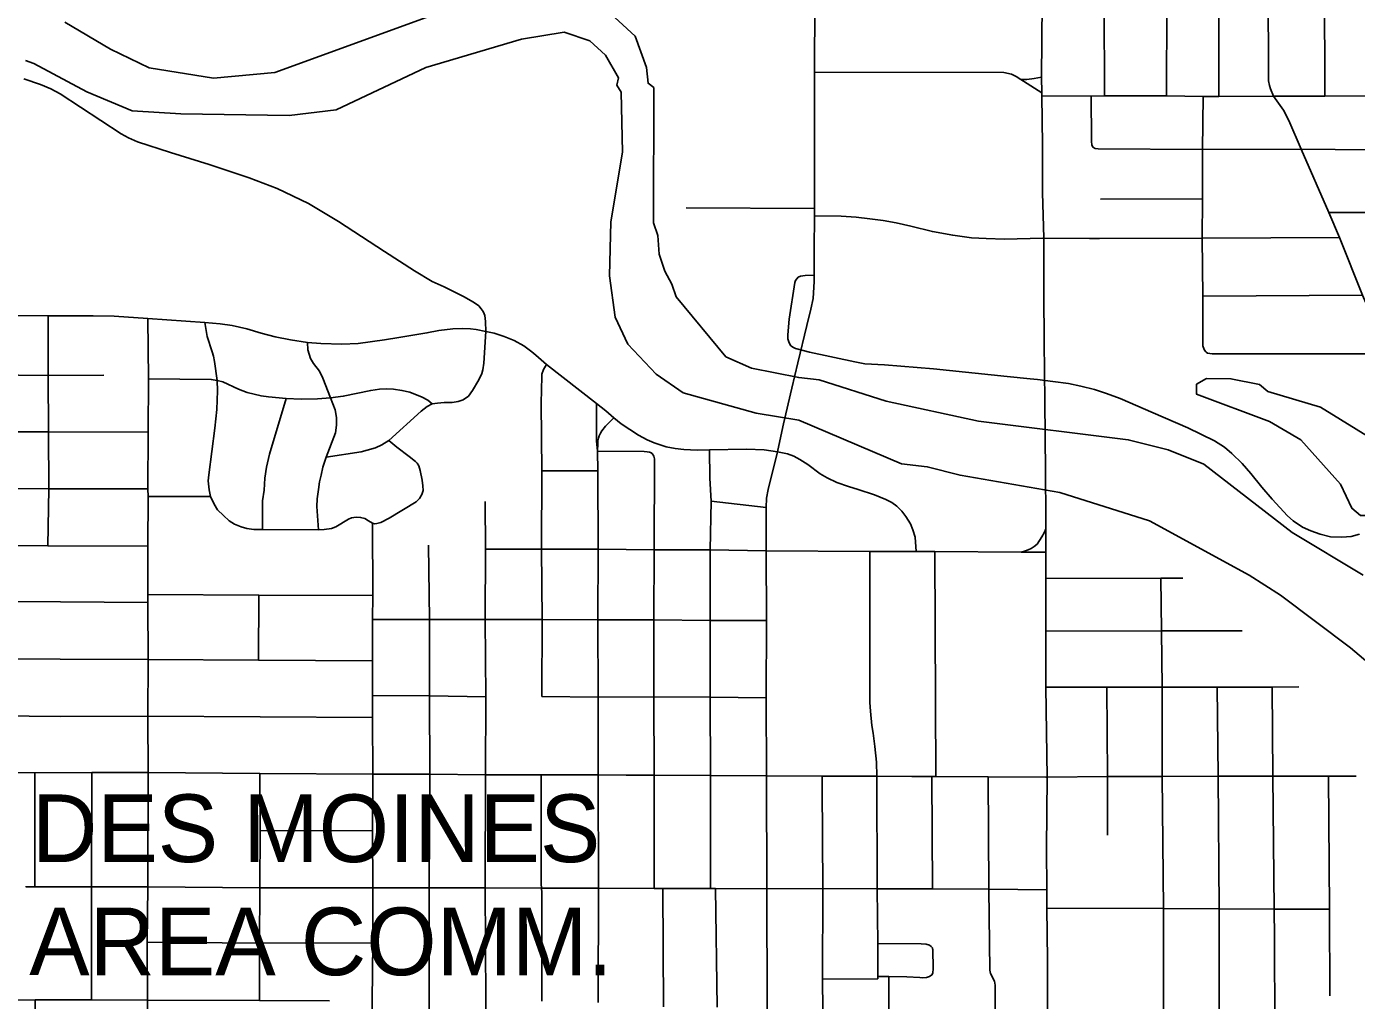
# Model space of a CAD drawing. Extents: x -1403959 to 81668, y -1400582 to 11018.
# Drawn here: x 7081.4 to 7223.9, y 8354.4 to 8458.9 of the extents above; entities that cross this region are included whole.
import ezdxf

# ---------------------------------------------------------------- set-up
doc = ezdxf.new("R2010")
doc.units = 0
for name, color, linetype in [('tdCiSectNmbr', 7, 'Continuous'), ('tdCiSectTwpRng', 7, 'Continuous'), ('tdCoStrucSec', 7, 'Continuous'), ('tdCoSurfBitum', 7, 'Continuous')]:
    doc.layers.add(name, color=color, linetype=linetype)

msp = doc.modelspace()

# ---------------------------------------------------------------- linework, layer by layer
at = {"layer": 'tdCiSectNmbr'}
for points in [[(7165.83, 8431.54), (7165.83, 8432.21), (7165.83, 8435.02), (7165.86, 8438.57), (7165.86, 8439.36), (7165.87, 8454), (7165.91, 8461.53), (7165.92, 8461.77), (7165.94, 8469.53), (7165.94, 8470.99), (7165.96, 8480.28), (7165.96, 8480.78), (7165.96, 8480.78)], [(7190.84, 8351.52), (7190.85, 8358.78), (7190.77, 8364.35), (7190.75, 8366.29), (7190.74, 8370.74), (7190.79, 8378.4), (7190.66, 8388.02), (7190.66, 8394.05), (7190.64, 8399.68), (7190.66, 8402.51), (7190.64, 8405.03), (7190.64, 8406.28), (7190.62, 8411.12), (7190.55, 8418.76), (7190.49, 8425.02), (7190.43, 8430.21), (7190.43, 8434.35), (7190.43, 8435.97), (7190.43, 8436.2), (7190.3, 8441.07), (7190.28, 8446.2), (7190.21, 8451.46), (7190.21, 8451.76), (7190.2, 8453.47), (7190.26, 8461.4)], [(7081.1, 8453.29), (7082.89, 8452.67), (7084.01, 8452.19), (7085, 8451.66), (7091.53, 8447.39), (7092.32, 8446.94), (7093.3, 8446.53), (7096.85, 8445.39), (7100.99, 8444.08), (7105.26, 8442.67), (7108.25, 8441.51), (7111.63, 8439.9), (7114.84, 8437.97), (7119.76, 8434.77)], [(7119.76, 8434.77), (7122.98, 8432.7), (7124.89, 8431.56)], [(7124.89, 8431.56), (7126.16, 8430.96), (7128.23, 8429.95), (7129.31, 8429.33), (7129.88, 8428.93), (7130.15, 8428.62), (7130.36, 8428.32), (7130.46, 8428.09)], [(7165.04, 8426.84), (7165.48, 8428.57), (7165.72, 8429.71), (7165.83, 8431.54), (7165.83, 8431.54)], [(7077.82, 8427.88), (7077.82, 8427.88), (7083.71, 8427.87)], [(7083.71, 8427.87), (7083.71, 8427.87), (7088.55, 8427.86)], [(7088.55, 8427.86), (7088.55, 8427.86), (7090.81, 8427.82), (7094.41, 8427.56)], [(7130.46, 8428.09), (7130.51, 8427.9), (7130.6, 8427.25), (7130.64, 8426.19)], [(7094.41, 8427.56), (7094.41, 8427.56), (7100.5, 8427.16), (7102.15, 8427), (7103.44, 8426.82), (7105.01, 8426.46), (7106.56, 8426.01), (7108.05, 8425.6), (7109.71, 8425.27), (7111.52, 8425.01), (7112.95, 8424.88), (7115.19, 8424.83), (7116.94, 8424.89), (7119.76, 8425.27), (7121.31, 8425.53), (7124.31, 8426.02), (7125.6, 8426.27), (7127.09, 8426.46), (7128.16, 8426.49), (7128.98, 8426.46), (7129.61, 8426.39), (7130.64, 8426.19), (7131.52, 8425.99), (7132.59, 8425.66), (7133.68, 8425.21), (7134.69, 8424.64), (7135.55, 8424), (7136, 8423.64)], [(7162.25, 8414.95), (7162.53, 8416.29), (7163.42, 8420.12), (7164.07, 8422.82), (7165.04, 8426.84), (7165.04, 8426.84)], [(7136, 8423.64), (7136, 8423.64), (7137.14, 8422.63)], [(7137.14, 8422.63), (7142.48, 8418.45), (7143.48, 8417.67)], [(7143.48, 8417.67), (7144.36, 8416.93), (7145.13, 8416.29), (7146.99, 8415.06), (7147.93, 8414.58)], [(7147.93, 8414.58), (7148.67, 8414.24), (7149.96, 8413.82), (7150.93, 8413.62), (7151.86, 8413.52), (7153.3, 8413.47), (7154.59, 8413.48)], [(7154.59, 8413.48), (7158.58, 8413.55), (7160.48, 8413.49), (7161.89, 8413.29)], [(7161.89, 8413.29), (7162.25, 8414.95)], [(7160.75, 8366.41), (7160.71, 8378.52), (7160.69, 8386.9), (7160.7, 8395.2), (7160.69, 8402.67), (7160.69, 8407.3), (7160.73, 8408.3), (7160.88, 8409.23), (7161.89, 8413.29), (7161.89, 8413.29)], [(7160.9, 8332.52), (7160.9, 8332.91), (7160.81, 8342.15), (7160.77, 8353.7), (7160.75, 8366.4), (7160.75, 8366.41)]]:
    msp.add_lwpolyline(points, dxfattribs=at)
at = {"layer": 'tdCiSectTwpRng'}
for points in [[(7203.6, 8451.44), (7203.63, 8461.33), (7203.7, 8468.61), (7203.65, 8475.78)], [(7209.19, 8451.4), (7209.18, 8475.79)], [(7214.53, 8453.07), (7214.48, 8463.58), (7214.32, 8475.75)], [(7220.56, 8451.42), (7220.53, 8463.58), (7220.47, 8475.75), (7220.47, 8475.75)], [(7196.95, 8451.44), (7196.89, 8461.33)], [(7165.87, 8454), (7186.14, 8453.94), (7186.96, 8453.78), (7187.49, 8453.53), (7187.97, 8453.21), (7188.67, 8452.76), (7190.21, 8451.76)], [(7190.2, 8453.47), (7189.42, 8453.32), (7188.63, 8453.22), (7187.97, 8453.21)], [(7215.06, 8451.41), (7214.75, 8452.19), (7214.63, 8452.56), (7214.53, 8453.07)], [(7190.21, 8451.46), (7195.5, 8451.42), (7196.95, 8451.44)], [(7195.54, 8446.74), (7195.5, 8451.42)], [(7196.95, 8451.44), (7203.6, 8451.44), (7207.5, 8451.4), (7209.19, 8451.4), (7215.06, 8451.41)], [(7207.48, 8429.98), (7207.41, 8436.19), (7207.45, 8440.42), (7207.43, 8445.71), (7207.5, 8451.4)], [(7215.06, 8451.41), (7220.56, 8451.42)], [(7216.7, 8448.82), (7216.12, 8449.92), (7215.59, 8450.68), (7215.06, 8451.41)], [(7220.56, 8451.42), (7226.51, 8451.46), (7226.69, 8451.46), (7238.02, 8451.41), (7238.64, 8451.46), (7238.73, 8451.47), (7239.15, 8451.53), (7257.3, 8451.54)], [(7239.56, 8390.34), (7238.74, 8391.63), (7238.25, 8392.48), (7236.67, 8395.45), (7236.13, 8396.61), (7235.89, 8397.32), (7235.61, 8398.39), (7235.52, 8399.05), (7235.45, 8399.68), (7235.3, 8403.2), (7235.2, 8405.07), (7235.07, 8406.18), (7234.84, 8407.02), (7234.45, 8408.15), (7234.01, 8409.26), (7233.75, 8409.8), (7230.61, 8416.45), (7227.27, 8423.78), (7226.73, 8425.13), (7224.61, 8430.06), (7222.12, 8436.26), (7220.99, 8438.93), (7218.03, 8445.72), (7216.7, 8448.82)], [(7195.54, 8446.74), (7195.54, 8446.57), (7195.59, 8446.21), (7195.7, 8445.95), (7195.93, 8445.82), (7196.27, 8445.77), (7207.43, 8445.71), (7218.03, 8445.72)], [(7218.03, 8445.72), (7232.55, 8445.59), (7238.68, 8445.5), (7238.7, 8445.5), (7249.96, 8445.55), (7256.78, 8445.52), (7262.99, 8445.5), (7269.09, 8445.5), (7272.28, 8445.5), (7275.16, 8445.51), (7277.24, 8445.49)], [(7152.1, 8439.44), (7165.86, 8439.36)], [(7196.53, 8440.39), (7207.45, 8440.42)], [(7165.86, 8438.57), (7168.73, 8438.55), (7170.32, 8438.44), (7171.8, 8438.28), (7173.22, 8438.08), (7174.61, 8437.85), (7176.18, 8437.49), (7178.5, 8436.9), (7180.68, 8436.51), (7182.7, 8436.24), (7184.26, 8436.14), (7186.24, 8436.08), (7190.33, 8436.2), (7190.43, 8436.2), (7195.35, 8436.17)], [(7220.99, 8438.93), (7229.25, 8438.96)], [(7195.35, 8436.17), (7196.4, 8436.16), (7207.41, 8436.19), (7222.12, 8436.26)], [(7165.83, 8432.21), (7164.87, 8432.19), (7164.35, 8432.13), (7164.12, 8431.99), (7163.96, 8431.83), (7163.84, 8431.66), (7163.74, 8431.44), (7163.16, 8427.49), (7162.99, 8425.84), (7163.01, 8425.39), (7163.14, 8424.97), (7163.32, 8424.65), (7163.6, 8424.47), (7163.82, 8424.37), (7165.33, 8423.98), (7170.19, 8422.94), (7171.26, 8422.73), (7173.36, 8422.59), (7178.62, 8422.17), (7186.52, 8421.34), (7188.96, 8421.12), (7189.77, 8421.02), (7191.4, 8420.82), (7193.1, 8420.6), (7194.39, 8420.31), (7195.88, 8419.95), (7197.15, 8419.53), (7198.62, 8418.98), (7202.17, 8417.45), (7205.88, 8415.86), (7208.72, 8414.47), (7209.79, 8413.76), (7210.6, 8413.08), (7211.7, 8412.01), (7212.63, 8410.96), (7213.8, 8409.47), (7214.93, 8408.2), (7215.72, 8407.31), (7216.54, 8406.4), (7217.17, 8405.86), (7218.16, 8405.21), (7219.06, 8404.79), (7220.05, 8404.43), (7221.16, 8404.17), (7222.39, 8404.12), (7223.38, 8404.21), (7224.28, 8404.43)], [(7207.48, 8429.98), (7224.61, 8430.06)], [(7207.84, 8423.97), (7207.75, 8424.04), (7207.61, 8424.25), (7207.48, 8424.65), (7207.48, 8429.98)], [(7083.76, 8415.42), (7083.71, 8421.47), (7083.71, 8427.87)], [(7094.45, 8415.38), (7094.48, 8421.11), (7094.41, 8427.56)], [(7100.5, 8427.16), (7100.76, 8425.65), (7101.3, 8423.99), (7101.44, 8423.52), (7101.56, 8422.96), (7101.83, 8420.93)], [(7101.83, 8420.93), (7102.44, 8420.8), (7104.12, 8420.01), (7105.06, 8419.65), (7106.55, 8419.27), (7107.33, 8419.16), (7109.24, 8418.98), (7110.83, 8418.93), (7112.6, 8418.96), (7114, 8419.08), (7115.35, 8419.24), (7118.3, 8419.86), (7119.23, 8420), (7119.96, 8420.04), (7120.74, 8419.98), (7121.63, 8419.86), (7122.49, 8419.66), (7123.8, 8419.14), (7124.4, 8418.81), (7124.87, 8418.41), (7125.46, 8418.5), (7126.16, 8418.55), (7127.02, 8418.57), (7127.65, 8418.67), (7128.22, 8418.86), (7128.77, 8419.25), (7129.19, 8419.84), (7129.88, 8420.98), (7130.21, 8421.66), (7130.31, 8422.06), (7130.42, 8422.77), (7130.64, 8426.19)], [(7112.69, 8404.92), (7112.53, 8407.42), (7112.57, 8408.23), (7112.69, 8409.25), (7112.79, 8410.04), (7112.97, 8410.78), (7113.16, 8411.62), (7113.53, 8412.72), (7114.51, 8415.32), (7114.64, 8416.13), (7114.62, 8416.97), (7114.49, 8417.78), (7114, 8419.08), (7113.17, 8421.18), (7112.79, 8421.93), (7112.16, 8422.74), (7111.84, 8423.28), (7111.69, 8423.75), (7111.57, 8424.2), (7111.52, 8425.01)], [(7207.84, 8423.97), (7207.98, 8423.86), (7208.49, 8423.77), (7227.27, 8423.78)], [(7072.96, 8422.49), (7073.32, 8422.48), (7073.63, 8422.45), (7073.94, 8422.37), (7074.23, 8422.27), (7074.52, 8422.13), (7074.93, 8421.92), (7075.37, 8421.76), (7075.82, 8421.63), (7076.28, 8421.55), (7076.75, 8421.52), (7077.22, 8421.53), (7077.33, 8421.53), (7083.71, 8421.47), (7089.68, 8421.5)], [(7136.63, 8387.08), (7136.66, 8395.28), (7136.6, 8402.82), (7136.62, 8411.23), (7136.58, 8418.49), (7136.62, 8421.37), (7136.65, 8421.59), (7136.8, 8422.09), (7137.14, 8422.63)], [(7094.48, 8421.11), (7101.2, 8421.05), (7101.83, 8420.93)], [(7101.83, 8420.93), (7101.87, 8419.81), (7101.8, 8417.82), (7101.6, 8415.81), (7100.95, 8410.81), (7100.89, 8410.16), (7100.97, 8409.19), (7101.13, 8408.47), (7101.51, 8407.68), (7101.88, 8407.07), (7102.5, 8406.44), (7103.11, 8405.86), (7103.71, 8405.51), (7104.42, 8405.22), (7105, 8405.06), (7105.75, 8404.96), (7106.69, 8404.96), (7112.69, 8404.92), (7113.32, 8404.94), (7114.09, 8405.06), (7114.54, 8405.24), (7115.93, 8406.05), (7116.25, 8406.2), (7116.75, 8406.27), (7117.21, 8406.24), (7117.65, 8406.12), (7118.04, 8405.89), (7118.48, 8405.64)], [(7106.69, 8404.96), (7106.71, 8408.02), (7106.87, 8409.17), (7106.94, 8410.44), (7107.13, 8411.64), (7107.46, 8413.04), (7109.24, 8418.98)], [(7113.53, 8412.72), (7117.28, 8413.29), (7117.92, 8413.44), (7118.81, 8413.7), (7119.5, 8414.02), (7120.25, 8414.5), (7123.71, 8417.63), (7124.35, 8418.12), (7124.87, 8418.41)], [(7142.48, 8418.45), (7142.48, 8417.3), (7142.48, 8415.77), (7142.48, 8414.89), (7142.51, 8414.44)], [(7060.72, 8416.52), (7074.91, 8416.46), (7075.24, 8416.41), (7075.44, 8416.22), (7075.63, 8415.8), (7075.8, 8415.53), (7076.01, 8415.43), (7076.53, 8415.42), (7083.76, 8415.42), (7094.45, 8415.38)], [(7142.64, 8414.43), (7142.65, 8414.45), (7142.7, 8414.73), (7142.79, 8415), (7142.91, 8415.26), (7143.05, 8415.51), (7143.46, 8416.02), (7144.36, 8416.93)], [(7083.7, 8403.19), (7083.78, 8409.32), (7083.76, 8415.42)], [(7094.41, 8409.31), (7094.45, 8415.38)], [(7118.48, 8405.64), (7118.72, 8405.57), (7118.94, 8405.59), (7119.39, 8405.69), (7120.27, 8406.17), (7123.17, 8407.91), (7123.52, 8408.28), (7123.77, 8408.71), (7123.91, 8409.14), (7123.89, 8409.64), (7123.81, 8410.24), (7123.61, 8411.28), (7123.44, 8411.76), (7123.26, 8412.07), (7123.08, 8412.24), (7122.42, 8412.77), (7121.11, 8413.77), (7120.25, 8414.5)], [(7142.51, 8414.44), (7142.59, 8413.34)], [(7142.67, 8354.23), (7142.72, 8366.47), (7142.69, 8378.62), (7142.69, 8386.95), (7142.62, 8395.25), (7142.67, 8402.82), (7142.63, 8411.23), (7142.59, 8413.34), (7142.62, 8414.16), (7142.64, 8414.43)], [(7142.59, 8413.34), (7147.59, 8413.32), (7147.91, 8413.29), (7148.19, 8413.25), (7148.28, 8413.2)], [(7148.66, 8402.77), (7148.7, 8412.51), (7148.63, 8412.81), (7148.45, 8413.09), (7148.28, 8413.2)], [(7154.63, 8410.46), (7154.59, 8413.48)], [(7165.15, 8411.91), (7164.27, 8412.45), (7163.63, 8412.8), (7162.97, 8413.05), (7161.89, 8413.29)], [(7136.62, 8411.23), (7142.63, 8411.23)], [(7176.76, 8402.6), (7176.64, 8404.11), (7176.41, 8404.9), (7176.16, 8405.56), (7175.66, 8406.35), (7175.21, 8406.92), (7174.69, 8407.45), (7174.14, 8407.85), (7173.49, 8408.18), (7172.28, 8408.65), (7170.53, 8409.22), (7169.49, 8409.57), (7168.24, 8409.99), (7167.2, 8410.47), (7166.48, 8410.93), (7165.15, 8411.91)], [(7076.09, 8408.97), (7076.43, 8409.17), (7076.95, 8409.34), (7083.78, 8409.32)], [(7083.78, 8409.32), (7094.41, 8409.31)], [(7094.41, 8366.62), (7094.44, 8378.9), (7094.42, 8384.92), (7094.44, 8391), (7094.41, 8397.11), (7094.4, 8397.97), (7094.4, 8403.15), (7094.43, 8408.48), (7094.41, 8409.31)], [(7154.78, 8407.99), (7154.63, 8410.46)], [(7094.43, 8408.48), (7101.13, 8408.47)], [(7130.61, 8402.83), (7130.57, 8407.95)], [(7154.67, 8402.75), (7154.78, 8407.99)], [(7154.78, 8407.99), (7160.69, 8407.3)], [(7118.48, 8395.3), (7118.51, 8397.85), (7118.48, 8405.64)], [(7188.01, 8402.51), (7188.38, 8402.61), (7188.75, 8402.75), (7189.09, 8402.92), (7189.41, 8403.14), (7189.71, 8403.39), (7189.99, 8403.77), (7190.24, 8404.17), (7190.46, 8404.59), (7190.64, 8405.03)], [(7064.47, 8403.32), (7083.7, 8403.19), (7094.4, 8403.15)], [(7124.6, 8395.28), (7124.47, 8403.27)], [(7130.6, 8378.65), (7130.65, 8387.01), (7130.56, 8395.3), (7130.61, 8402.83)], [(7130.61, 8402.83), (7136.6, 8402.82), (7142.67, 8402.82), (7148.66, 8402.77), (7154.67, 8402.75), (7160.69, 8402.67)], [(7148.68, 8378.59), (7148.65, 8387), (7148.63, 8395.27), (7148.66, 8402.77)], [(7154.73, 8378.55), (7154.68, 8386.95), (7154.68, 8395.2), (7154.67, 8402.75)], [(7160.69, 8402.67), (7171.78, 8402.59), (7176.76, 8402.6)], [(7172.53, 8378.48), (7172.49, 8379.98), (7172.34, 8381.68), (7172.16, 8383.09), (7172.02, 8383.93), (7171.87, 8385.45), (7171.8, 8386.4), (7171.78, 8402.59)], [(7176.76, 8402.6), (7178.77, 8402.57), (7188.01, 8402.51), (7188.65, 8402.51), (7190.66, 8402.51)], [(7178.87, 8378.45), (7178.77, 8402.57)], [(7190.64, 8399.68), (7202.98, 8399.73), (7205.35, 8399.73)], [(7203.54, 8329.44), (7203.53, 8329.89), (7203.46, 8335.58), (7203.42, 8340.47), (7203.28, 8351.57), (7203.28, 8364.31), (7203.13, 8378.46), (7203.11, 8388.02), (7203.06, 8394.07), (7202.98, 8399.73)], [(7094.4, 8397.97), (7106.3, 8397.91), (7118.51, 8397.85)], [(7106.28, 8390.93), (7106.3, 8397.91)], [(7066.53, 8397.23), (7085.03, 8397.18), (7094.41, 8397.11)], [(7118.51, 8366.52), (7118.51, 8366.52), (7118.47, 8372.64), (7118.52, 8378.72), (7118.47, 8384.77), (7118.49, 8387.13), (7118.48, 8390.85), (7118.48, 8395.3)], [(7118.48, 8395.3), (7124.6, 8395.28), (7130.56, 8395.3), (7136.66, 8395.28), (7142.62, 8395.25), (7148.63, 8395.27), (7154.68, 8395.2), (7160.7, 8395.2)], [(7124.58, 8330.21), (7124.55, 8342.08), (7124.57, 8354.43), (7124.56, 8366.53), (7124.64, 8378.7), (7124.59, 8387.09), (7124.6, 8395.28)], [(7190.66, 8394.05), (7203.06, 8394.07), (7211.71, 8394.07)], [(7068.51, 8391.07), (7085.01, 8391.03), (7094.44, 8391)], [(7094.44, 8391), (7106.28, 8390.93), (7118.48, 8390.85)], [(7190.66, 8388.02), (7197.2, 8388.02), (7203.11, 8388.02), (7209.02, 8388.05), (7214.92, 8388.05), (7217.76, 8388.08)], [(7197.26, 8372.16), (7197.25, 8378.46), (7197.2, 8388.02)], [(7209.24, 8351.55), (7209.24, 8364.25), (7209.11, 8378.48), (7209.02, 8388.05)], [(7215.18, 8340.97), (7215.27, 8341.18), (7215.29, 8341.6), (7215.21, 8351.55), (7215.15, 8361.19), (7215.14, 8364.23), (7214.99, 8378.49), (7214.92, 8388.05)], [(7118.49, 8387.13), (7124.59, 8387.09)], [(7124.59, 8387.09), (7130.65, 8387.01)], [(7136.63, 8387.08), (7136.63, 8387.04)], [(7136.63, 8387.04), (7142.69, 8386.95)], [(7142.69, 8386.95), (7148.65, 8387), (7154.68, 8386.95), (7160.69, 8386.9)], [(7072.05, 8385.02), (7078.33, 8384.97), (7085, 8384.89), (7094.42, 8384.92), (7118.47, 8384.77)], [(7070.22, 8378.95), (7076.28, 8378.88), (7076.32, 8378.88), (7082.3, 8378.84), (7088.4, 8378.89), (7094.44, 8378.9)], [(7082.3, 8366.62), (7082.3, 8378.84)], [(7088.36, 8354.5), (7088.36, 8366.62), (7088.4, 8378.89)], [(7094.44, 8378.9), (7106.41, 8378.79)], [(7106.41, 8378.79), (7118.52, 8378.72), (7124.64, 8378.7), (7130.6, 8378.65)], [(7106.45, 8372.68), (7106.41, 8378.79)], [(7130.79, 8330.16), (7130.65, 8331.29), (7130.63, 8342.1), (7130.62, 8345.37), (7130.64, 8354.37), (7130.56, 8366.53), (7130.6, 8378.65)], [(7130.6, 8378.65), (7136.58, 8378.65), (7142.69, 8378.62), (7142.69, 8378.62)], [(7136.59, 8366.49), (7136.56, 8366.93), (7136.58, 8378.65)], [(7142.69, 8378.62), (7145.69, 8378.6)], [(7145.69, 8378.6), (7148.68, 8378.59), (7154.73, 8378.55), (7160.71, 8378.52), (7160.71, 8378.52)], [(7148.69, 8366.46), (7148.68, 8378.59)], [(7154.7, 8366.44), (7154.73, 8378.55)], [(7160.71, 8378.52), (7166.67, 8378.48), (7172.53, 8378.48), (7176.29, 8378.47)], [(7166.81, 8350.68), (7166.76, 8353.4), (7166.73, 8356.72), (7166.75, 8366.45), (7166.67, 8377.35), (7166.67, 8378.48)], [(7172.66, 8357), (7172.66, 8360.55), (7172.59, 8366.42), (7172.53, 8378.48)], [(7176.29, 8378.47), (7178.44, 8378.46), (7178.87, 8378.45), (7184.47, 8378.41), (7190.66, 8378.4), (7190.79, 8378.4), (7197.25, 8378.46), (7203.13, 8378.46), (7209.11, 8378.48), (7214.99, 8378.49), (7220.95, 8378.48), (7223.92, 8378.48)], [(7178.5, 8366.41), (7178.44, 8378.46)], [(7185.21, 8350.6), (7185.24, 8356.09), (7185.15, 8356.51), (7184.73, 8357.32), (7184.64, 8357.69), (7184.53, 8366.36), (7184.47, 8378.41)], [(7221.1, 8354.93), (7221.05, 8364.23), (7220.95, 8378.48)], [(7106.41, 8366.52), (7106.45, 8372.68), (7106.45, 8372.68)], [(7106.45, 8372.68), (7118.47, 8372.64)], [(7081.32, 8366.61), (7081.32, 8366.61), (7082.3, 8366.62), (7088.36, 8366.62), (7094.41, 8366.62), (7106.41, 8366.52), (7118.51, 8366.52)], [(7094.36, 8354.48), (7094.34, 8360.7), (7094.41, 8366.62)], [(7106.39, 8354.45), (7106.38, 8360.58), (7106.41, 8366.52)], [(7118.52, 8330.24), (7118.48, 8337.01), (7118.52, 8342.18), (7118.52, 8342.58), (7118.45, 8354.41), (7118.53, 8360.62), (7118.51, 8366.52)], [(7118.51, 8366.52), (7124.56, 8366.53), (7130.56, 8366.53), (7136.59, 8366.49), (7142.72, 8366.47)], [(7136.59, 8366.48), (7136.59, 8366.49), (7136.59, 8366.49)], [(7136.63, 8354.37), (7136.62, 8366.01), (7136.59, 8366.48)], [(7142.72, 8366.47), (7148.69, 8366.46), (7149.62, 8366.46), (7154.7, 8366.44), (7155.24, 8366.44), (7160.75, 8366.4)], [(7149.67, 8353.76), (7149.62, 8366.46)], [(7155.41, 8353.72), (7155.24, 8366.44)], [(7160.75, 8366.4), (7166.75, 8366.45), (7172.59, 8366.42), (7178.5, 8366.41), (7184.53, 8366.36), (7190.75, 8366.29)], [(7190.77, 8364.35), (7203.28, 8364.31), (7209.24, 8364.25), (7215.14, 8364.23), (7221.05, 8364.23)], [(7094.34, 8360.7), (7106.38, 8360.58), (7118.53, 8360.62)], [(7172.66, 8360.55), (7177.3, 8360.52), (7177.82, 8360.48), (7178.2, 8360.37), (7178.38, 8360.23), (7178.51, 8360.07)], [(7177.16, 8356.9), (7177.46, 8356.88), (7177.86, 8356.9), (7178.19, 8357), (7178.44, 8357.18), (7178.55, 8357.37), (7178.58, 8357.85), (7178.53, 8359.92), (7178.52, 8359.97)], [(7178.51, 8360.07), (7178.52, 8359.97)], [(7166.73, 8356.72), (7172.66, 8356.76)], [(7172.66, 8357), (7172.66, 8357)], [(7172.66, 8356.76), (7172.66, 8357)], [(7172.66, 8357), (7173.83, 8357), (7175.76, 8356.97), (7177.16, 8356.9)], [(7173.84, 8350.61), (7173.83, 8357)], [(7077.95, 8354.48), (7077.95, 8354.48), (7082.33, 8354.5)], [(7082.26, 8342.38), (7082.31, 8348.4), (7082.33, 8354.5)], [(7082.33, 8354.5), (7082.33, 8354.5), (7088.36, 8354.5), (7094.36, 8354.48), (7106.39, 8354.45), (7113.89, 8354.41)], [(7094.27, 8342.29), (7094.31, 8348.35), (7094.36, 8354.48)]]:
    msp.add_lwpolyline(points, dxfattribs=at)
at = {"layer": 'tdCoSurfBitum'}
for points in [[(7130.93, 8462.31), (7108.01, 8453.96), (7101.44, 8453.36), (7094.55, 8454.45), (7090.42, 8456.45), (7085.52, 8459.37)], [(7224.68, 8400.04), (7217.05, 8404.63), (7207.58, 8411.96), (7203.76, 8413.49), (7199.49, 8414.57), (7183.45, 8416.56), (7173.53, 8418.71), (7166.35, 8421), (7164.18, 8421.24), (7159.11, 8422.24), (7156.36, 8423.47), (7151.03, 8429.89), (7150.57, 8431.27), (7149.81, 8432.65), (7149.2, 8434.48), (7149.06, 8436.46), (7148.6, 8437.84), (7148.63, 8452.34), (7148.02, 8452.8), (7147.87, 8454.48), (7146.65, 8457.84), (7143.15, 8461.06)], [(7227.27, 8388.9), (7223.3, 8392.26), (7215.82, 8397.91), (7212.46, 8400.05), (7201.77, 8405.86), (7192.15, 8408.92), (7181.46, 8410.76), (7177.95, 8411.68), (7175.2, 8411.99), (7164.17, 8416.66), (7159.59, 8417.43), (7151.8, 8419.6), (7148.9, 8421.59), (7145.85, 8424.81), (7144.48, 8427.71), (7143.88, 8432.14), (7144.04, 8437.95), (7145.28, 8445.43), (7145.14, 8451.84), (7144.68, 8452.6), (7144.84, 8453.37), (7143.47, 8455.81), (7141.79, 8457.35), (7139.04, 8458.27), (7134.46, 8457.52), (7124.21, 8454.5), (7114.58, 8449.95), (7109.54, 8449.35), (7097.93, 8449.54), (7092.73, 8449.86), (7087.85, 8451.87), (7082.2, 8454.93), (7081.29, 8455.24)], [(7224.38, 8406.46), (7223.46, 8407.22), (7222.24, 8409.82), (7217.97, 8414.55), (7214.61, 8416.54), (7206.82, 8419.45), (7206.82, 8420.52), (7207.89, 8421.13), (7210.49, 8421.12), (7213.54, 8420.51), (7214.46, 8419.75), (7220.11, 8418.06), (7226.06, 8414.39), (7227.43, 8412.71), (7228.65, 8410.42), (7228.5, 8408.13), (7225.45, 8406.46), (7224.38, 8406.46)]]:
    msp.add_lwpolyline(points, dxfattribs=at)

# ---------------------------------------------------------------- texts
at = {"layer": 'tdCoStrucSec'}
for s, p in [('DES MOINES', (7081.99, 8369.28)), ('DES MOINES', (7081.99, 8369.28)), ('AREA COMM.', (7081.69, 8357.15)), ('AREA COMM.', (7081.69, 8357.15))]:
    msp.add_text(s, height=7.255, rotation=359.9948, dxfattribs=at).set_placement(p)

doc.saveas('drawing.dxf')
